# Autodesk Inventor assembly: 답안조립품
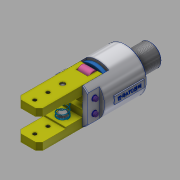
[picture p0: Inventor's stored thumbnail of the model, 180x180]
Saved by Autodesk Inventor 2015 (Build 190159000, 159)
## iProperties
Created: 2019-02
Part Number: 답안조립품
Document SubType Name: Assembly
Designer: SCD-A18
Author: SCD-A18
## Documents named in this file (11)
- C:\Users\SCD-A18\Downloads\490207V1002\답안조립품.iam
- C:\Users\SCD-A18\Downloads\490207V1002\본체.ipt
- C:\Users\SCD-A18\Downloads\490207V1002\O-링.ipt
- C:\Users\SCD-A18\Downloads\490207V1002\피스톤.ipt
- C:\Users\SCD-A18\Downloads\490207V1002\핑거.ipt
- C:\Users\SCD-A18\Downloads\490207V1002\평행핀 6x28.ipt
- C:\Users\SCD-A18\Downloads\490207V1002\부시.ipt
- C:\Users\SCD-A18\Downloads\490207V1002\핀.ipt
- C:\Users\SCD-A18\Downloads\490207V1002\E-링.ipt
- C:\Users\SCD-A18\Downloads\490207V1002\가이드핀.ipt
- C:\Users\SCD-A18\Downloads\490207V1002\스프링.ipt
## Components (13 placed, 6 different names)
1. O-링:1
2. O-링:2
3. 피스톤:1
4. 핑거:1 — 각도:1
5. 핑거:2 — 각도:2
6. 핀:1 — 플러쉬:2
7. 핀:2 — 플러쉬:1
8. E-링:1
9. E-링:2
10. E-링:3
11. E-링:4
12. 가이드핀:1
13. 가이드핀:2
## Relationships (4: Flush 2, Angle 2)
- 플러쉬:1 [Flush]: 핀:2
- 플러쉬:2 [Flush]: 핀:1
- 각도:1 [Angle]: 핑거:1
- 각도:2 [Angle]: 핑거:2
